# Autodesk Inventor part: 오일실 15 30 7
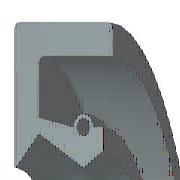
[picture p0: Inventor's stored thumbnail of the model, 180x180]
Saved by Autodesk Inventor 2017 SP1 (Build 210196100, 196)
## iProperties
IsCustomPart: 1
Created: 2012-02
Part Number: 오일실 15 30 7
Material: 고무
Description: 오일-실
Document SubType Name: Modeling
Standard: KS B 2804
Designer: mduedu
Standards Organization: KS
Language: ko-KR
Size Designation: D - 15 30 7
Categories: <MemberInstance><Categories><Category DisplayName="샤프트 부품" InternalName="7f7aeb1f-a693-4053-b835-cee3144e0d98" Mnemonic="SHFT"><Category DisplayName="실링" Intern
Density: 0.93 g/cm^3
Appearance: 고무 - 검은색 - 버전 1.1
Author: mduedu
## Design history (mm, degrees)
revolve "본체" stored, may be unused: angle "d17" = 90 deg
revolve "스프링1" stored, may be unused: angle "d18" = 90 deg
body "Solid1"
sketch "스케치1"
  geometry: L1 (0, 15)-(7, 15); L2 (7, 13.25)-(1.75, 13.25); L3 (1.75, 9.25)-(4.9, 7.5); L4 (4.9, 7.5)-(0, 7.5); L5 (0, 0)-(9.586, 0) reference; L6 (4.9, 7.5)-(6.3, 8.375); L7 (0, 18)-(0, -3) reference; L8 (-1.941, 0)-(11.507, 0) reference; L9 (4.2, 9.6)-(1.75, 10.09); L10 (1.75, 10.09)-(1.75, 13.25); L11 (0, 15)-(0, 7.588); L12 (4.9, 7.5)-(0, 7.5); L13 (1.75, 9.25)-(0.152, 7.528); L14 (7, 15)-(7, 13.25); L15 (5.6, 9.6)-(6.3, 9.6); L16 (6.3, 9.6)-(6.3, 8.375); C1 r 0.455 at (4.9, 9.6); A1 r 0.7 centre (4.9, 9.6) between (5.6, 9.6) and (4.2, 9.6); A2 r 0.088 centre (0.088, 7.588) between (0, 7.588) and (0.152, 7.528); 1 further point
  constraints: 28 end point, 5 horizontal alignment, 5 point on line, 4 point on circle, 4 vertical alignment, 3 centre point, 3 tangent, 2 collinear, 2 horizontal, 2 perpendicular, 1 coincident, 1 parallel
  dimensions: "d0" = 30 diameter of L1 L5 (= SD2); "d1" = 1.75 distance of L1.end L2.start (= SD); "d2" = 0.91 diameter of C1 (= SPDI); "d3" = 1.4 diameter of A1 (= SPDA); "d4" = 15 diameter of L3.end L5 (= NND); "d5" = 18.5 diameter of L3.start L5 (= TKDM); "d7" = 20.18 diameter of L9.end L5 (= TKDM + 0.24 x SWDT); "d8" = 1.75 distance between parallel lines of L11 L10 (= SD); "d9" = 4.9 distance from line of L11 C1.centre (= SPDST); "d10" = 19.2 diameter of C1.centre L5 (= HLDM); "d11" = 0.0875 radius of A2 (= 0.25 x LAB); "d12" = 6.3 distance between parallel lines of L11 L16 (= SDI); "d13" = 16.75 diameter of L6.end L5 (= ABDM); "d14" = 7 distance from line of L11 L1.end (= SWDT)
fillet "모깎기1" dims "d6" = 0.3 (= RR)
other parameters: "SD2" = 30 [user parameter; used in 1 equation term], "SWDT" = 7 [user parameter; used in 2 equation terms], "RR" = 0.3 [user parameter; used in 1 equation term], "SD" = 1.75 [user parameter; used in 2 equation terms], "NND" = 15 [user parameter; used in 1 equation term], "SPDA" = 1.4 [user parameter; used in 1 equation term], "SPDI" = 0.91 [user parameter; used in 1 equation term], "TKDM" = 18.5 [user parameter; used in 2 equation terms], "HLDM" = 19.2 [user parameter; used in 1 equation term], "ABDM" = 16.75 [user parameter; used in 1 equation term], "SDI" = 6.3 [user parameter; used in 1 equation term], "SPDST" = 4.9 [user parameter; used in 1 equation term], "LAB" = 0.35 [user parameter; used in 1 equation term], "d15" = 0, "d16" = 0, "d19" = 0
